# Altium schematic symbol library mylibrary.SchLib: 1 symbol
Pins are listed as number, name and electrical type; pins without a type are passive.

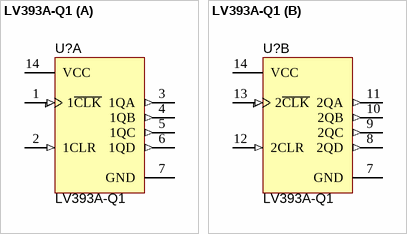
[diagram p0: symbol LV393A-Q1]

## LV393A-Q1
designator U?
dual 4 bit automotive up counter; Manufacturer: Used in BOM report; SymbolVersion: use current date i.e. 2008-05-20; SymbolCreator: Use a-id; CompType: Used in some BOM reports.  Useful for finding later.; U/M: EA, IN, or GM
pins on every part: 7 GND (power), 14 VCC (power)
part A pins: 1 1~{CLK} (in), 2 1CLR (in), 3 1QA (out), 4 1QB (out), 5 1QC (out), 6 1QD (out)
part B pins: 8 2QD (out), 9 2QC (out), 10 2QB (out), 11 2QA (out), 12 2CLR (in), 13 2~{CLK} (in)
